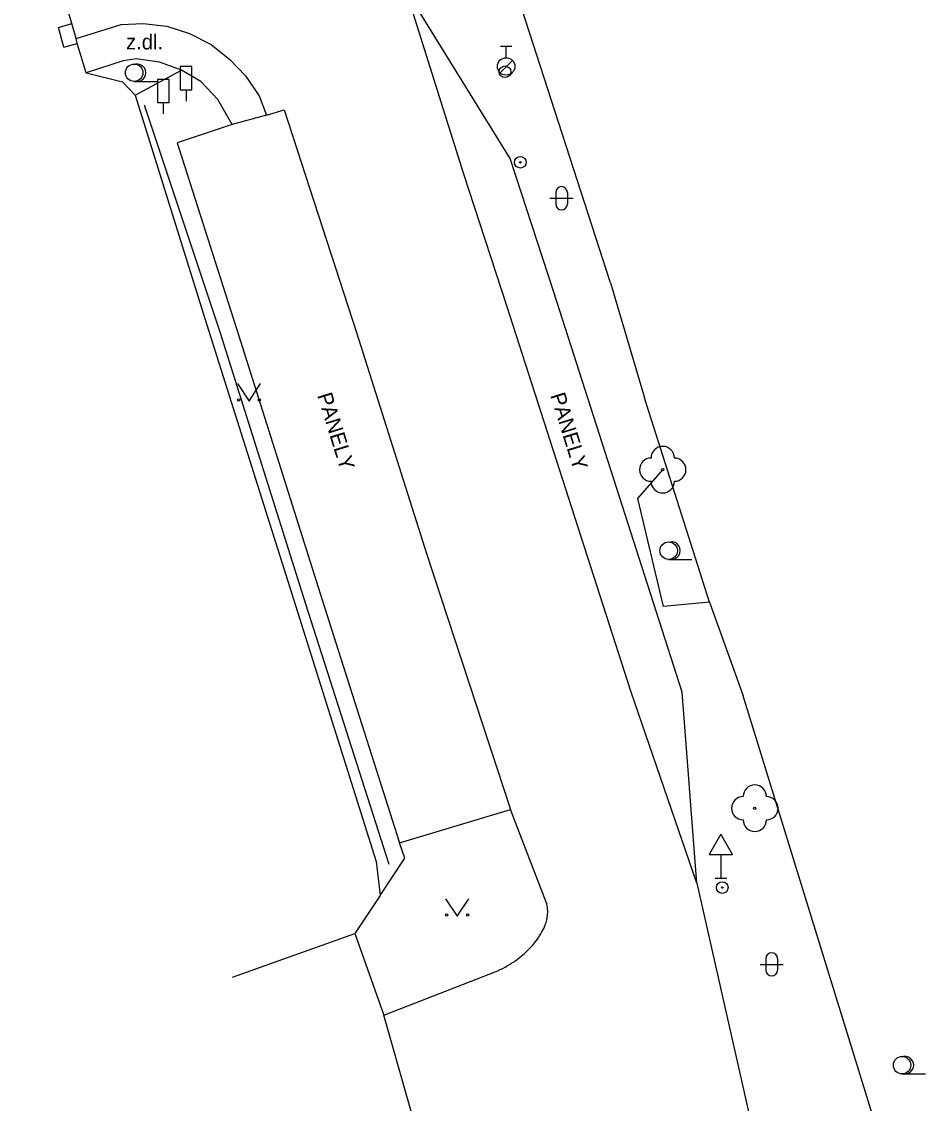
# Model space of a CAD drawing. Extents: x -539244 to -537359, y -1183785 to -1181851.
# Drawn here: x -538156.84 to -538117.99, y -1182044.68 to -1181998.19 of the extents above; entities that cross this region are included whole.
import ezdxf

# ---------------------------------------------------------------- set-up
doc = ezdxf.new("R2010")
doc.units = 0
for name, color, linetype in [('Vrstva 10', 7, 'Continuous'), ('Vrstva 11', 7, 'Continuous'), ('Vrstva 21', 7, 'Continuous'), ('Vrstva 22', 7, 'Continuous'), ('Vrstva 25', 7, 'Continuous'), ('Vrstva 28', 7, 'Continuous'), ('Vrstva 34', 7, 'Continuous'), ('Vrstva 36', 7, 'Continuous'), ('Vrstva 38', 7, 'Continuous'), ('Vrstva 40', 7, 'Continuous'), ('Vrstva 7', 7, 'Continuous'), ('Vrstva 8', 7, 'Continuous')]:
    doc.layers.add(name, color=color, linetype=linetype)

msp = doc.modelspace()

# ---------------------------------------------------------------- linework, layer by layer
at = {"layer": 'Vrstva 10'}
for points in [[(-538137.83, -1182004.75), (-538140.32, -1181996.81)], [(-538154.5, -1181998.92), (-538152.56, -1181998.32), (-538151.62, -1181998.27), (-538150.6, -1181998.39), (-538149.62, -1181998.71), (-538148.69, -1181999.17), (-538147.89, -1181999.82), (-538147.22, -1182000.53), (-538146.63, -1182001.38), (-538146.31, -1182002.21)], [(-538146.31, -1182002.21), (-538145.55, -1182001.99)], [(-538145.55, -1182001.99), (-538142.44, -1182011.55)], [(-538135.98, -1182010.41), (-538137.83, -1182004.75)], [(-538130.64, -1182027.01), (-538135.98, -1182010.41)], [(-538142.44, -1182011.55), (-538139.42, -1182021.1)], [(-538139.42, -1182021.1), (-538135.83, -1182032.05)], [(-538127.81, -1182035.22), (-538130.64, -1182027.01)], [(-538134.29, -1182036.03), (-538135.83, -1182032.05)], [(-538127.81, -1182035.22), (-538125.4, -1182045.87), (-538124.045, -1182050.07), (-538122.69, -1182054.27)], [(-538141.27, -1182040.89), (-538138.875, -1182039.96), (-538136.48, -1182039.03), (-538136.371, -1182038.985), (-538136.264, -1182038.937), (-538136.16, -1182038.886), (-538136.059, -1182038.832), (-538135.961, -1182038.776), (-538135.866, -1182038.719), (-538135.774, -1182038.66), (-538135.686, -1182038.601), (-538135.601, -1182038.541), (-538135.52, -1182038.481), (-538135.442, -1182038.42), (-538135.367, -1182038.36), (-538135.226, -1182038.239), (-538135.099, -1182038.12), (-538134.985, -1182038.004), (-538134.882, -1182037.893), (-538134.791, -1182037.785), (-538134.71, -1182037.682), (-538134.639, -1182037.584), (-538134.576, -1182037.491), (-538134.521, -1182037.402), (-538134.473, -1182037.319), (-538134.432, -1182037.239), (-538134.396, -1182037.165), (-538134.365, -1182037.094), (-538134.338, -1182037.028), (-538134.316, -1182036.965), (-538134.297, -1182036.907), (-538134.267, -1182036.797), (-538134.247, -1182036.7), (-538134.234, -1182036.615), (-538134.227, -1182036.542), (-538134.224, -1182036.477), (-538134.224, -1182036.42), (-538134.229, -1182036.322), (-538134.238, -1182036.248), (-538134.247, -1182036.193), (-538134.266, -1182036.111), (-538134.29, -1182036.03)]]:
    msp.add_lwpolyline(points, dxfattribs=at)
at = {"layer": 'Vrstva 11'}
msp.add_line((-538146.31, -1182002.21), (-538147.79, -1182002.62), dxfattribs=at)
for points in [[(-538135.84, -1182004.08), (-538140.32, -1181996.81)], [(-538149.96, -1182000.28), (-538150.92, -1181999.93), (-538151.91, -1181999.8), (-538152.47, -1181999.88), (-538154.06, -1182000.4)], [(-538147.79, -1182002.62), (-538148.41, -1182001.54), (-538149.13, -1182000.77), (-538149.96, -1182000.28)], [(-538147.79, -1182002.62), (-538150.15, -1182003.41)], [(-538150.15, -1182003.41), (-538147.52, -1182011.65)], [(-538133.96, -1182009.82), (-538135.84, -1182004.08)], [(-538128.44, -1182027.01), (-538133.96, -1182009.82)], [(-538147.52, -1182011.65), (-538143.83, -1182023.31)], [(-538143.83, -1182023.31), (-538140.59, -1182033.48)], [(-538127.81, -1182035.22), (-538128.44, -1182027.01)], [(-538140.59, -1182033.48), (-538135.83, -1182032.05)]]:
    msp.add_lwpolyline(points, dxfattribs=at)
at = {"layer": 'Vrstva 21'}
msp.add_line((-538151.96, -1182001.35), (-538149.96, -1182000.28), dxfattribs=at)
msp.add_lwpolyline([(-538127.27, -1182023.15), (-538129.25, -1182023.33), (-538130.35, -1182018.69), (-538129.28, -1182017.45)], dxfattribs=at)
at = {"layer": 'Vrstva 22'}
for centre in [(-538129.28, -1182017.45), (-538125.32, -1182032)]:
    msp.add_circle(centre, 0.05, dxfattribs=at)
for centre, start, end in [((-538129.28, -1182016.95), 0, 180), ((-538129.78, -1182017.45), 90, 270), ((-538128.78, -1182017.45), 270, 90), ((-538129.28, -1182017.95), 180, 0), ((-538125.32, -1182031.5), 0, 180), ((-538125.82, -1182032), 90, 270), ((-538124.82, -1182032), 270, 90), ((-538125.32, -1182032.5), 180, 0)]:
    msp.add_arc(centre, 0.5, start, end, dxfattribs=at)
at = {"layer": 'Vrstva 25'}
for centre, radius in [((-538135.4, -1182004.24), 0.25), ((-538135.4, -1182004.24), 0.0303), ((-538126.72, -1182035.41), 0.25), ((-538126.72, -1182035.41), 0.0303)]:
    msp.add_circle(centre, radius, dxfattribs=at)
at = {"layer": 'Vrstva 28'}
for p, q in [((-538136.26, -1181999.245), (-538135.76, -1181999.245)), ((-538136.01, -1181999.745), (-538136.01, -1181999.245)), ((-538136.268, -1182000.392), (-538135.738, -1181999.862))]:
    msp.add_line(p, q, dxfattribs=at)
for centre, radius in [((-538136.01, -1182000.12), 0.375), ((-538136.06, -1182000.35), 0.25)]:
    msp.add_circle(centre, radius, dxfattribs=at)
at = {"layer": 'Vrstva 34'}
for p, q in [((-538126.78, -1182033.984), (-538126.78, -1182035)), ((-538127.03, -1182035), (-538126.53, -1182035))]:
    msp.add_line(p, q, dxfattribs=at)
msp.add_lwpolyline([(-538127.28, -1182033.984), (-538126.28, -1182033.984), (-538126.78, -1182033.116)], close=True, dxfattribs=at)
at = {"layer": 'Vrstva 36'}
for p, q in [((-538152.002, -1182000.766), (-538151.002, -1182000.766)), ((-538134.129, -1182005.786), (-538133.129, -1182005.786)), ((-538133.88, -1182005.535), (-538133.88, -1182006.036)), ((-538133.379, -1182005.535), (-538133.379, -1182006.036)), ((-538129.025, -1182021.304), (-538128.025, -1182021.304)), ((-538124.847, -1182038.459), (-538124.847, -1182038.96)), ((-538124.346, -1182038.459), (-538124.346, -1182038.96)), ((-538125.096, -1182038.71), (-538124.096, -1182038.71)), ((-538118.988, -1182043.418), (-538117.988, -1182043.418))]:
    msp.add_line(p, q, dxfattribs=at)
for points in [[(-538147.565, -1182013.75), (-538147.065, -1182014.5), (-538146.565, -1182013.75)], [(-538138.619, -1182035.894), (-538138.119, -1182036.644), (-538137.619, -1182035.894)]]:
    msp.add_lwpolyline(points, dxfattribs=at)
for centre, radius in [((-538152.002, -1182000.391), 0.375), ((-538147.515, -1182014.45), 0.05), ((-538146.616, -1182014.45), 0.05), ((-538129.025, -1182020.929), 0.375), ((-538138.569, -1182036.594), 0.05), ((-538137.67, -1182036.594), 0.05), ((-538118.988, -1182043.043), 0.375)]:
    msp.add_circle(centre, radius, dxfattribs=at)
for centre, radius, start, end in [((-538151.877, -1182000.391), 0.375, 260.4059, 99.5941), ((-538133.629, -1182005.536), 0.25, 0, 180), ((-538133.629, -1182006.036), 0.25, 180, 0), ((-538128.9, -1182020.929), 0.375, 260.4059, 99.5941), ((-538124.596, -1182038.46), 0.25, 0, 180), ((-538124.596, -1182038.96), 0.25, 180, 0), ((-538118.863, -1182043.043), 0.375, 260.4059, 99.5941)]:
    msp.add_arc(centre, radius, start, end, dxfattribs=at)
at = {"layer": 'Vrstva 38'}
for p, q in [((-538149.77, -1182001.126), (-538149.77, -1182001.61)), ((-538150.75, -1182001.676), (-538150.75, -1182002.16))]:
    msp.add_line(p, q, dxfattribs=at)
for points in [[(-538150.019, -1182001.126), (-538149.521, -1182001.126), (-538149.521, -1182000.125), (-538150.019, -1182000.125)], [(-538150.999, -1182001.676), (-538150.501, -1182001.676), (-538150.501, -1182000.675), (-538150.999, -1182000.675)]]:
    msp.add_lwpolyline(points, close=True, dxfattribs=at)
at = {"layer": 'Vrstva 7'}
for p, q in [((-538131.53, -1182009.42), (-538140.59, -1181981.38)), ((-538155.256, -1181998.447), (-538154.68, -1181998.28)), ((-538155.026, -1181999.297), (-538155.256, -1181998.447)), ((-538155.026, -1181999.297), (-538154.45, -1181999.13)), ((-538127.27, -1182023.15), (-538130.06, -1182014.36)), ((-538119.8, -1182046.68), (-538125.82, -1182027.17)), ((-538147.773, -1182039.254), (-538142.51, -1182037.39))]:
    msp.add_line(p, q, dxfattribs=at)
for points in [[(-538154.5, -1181998.92), (-538154.68, -1181998.28)], [(-538154.45, -1181999.13), (-538154.5, -1181998.92)], [(-538154.06, -1182000.4), (-538152.5, -1182000.78), (-538151.96, -1182001.35)], [(-538151.96, -1182001.35), (-538148.96, -1182010.95)], [(-538151.57, -1182001.77), (-538148.32, -1182011.52)], [(-538148.96, -1182010.95), (-538145.31, -1182022.52)], [(-538148.32, -1182011.52), (-538144.63, -1182023.21)], [(-538145.31, -1182022.52), (-538141.6, -1182034.29)], [(-538144.63, -1182023.21), (-538141.06, -1182034.41)], [(-538141.42, -1182035.75), (-538140.36, -1182034.15), (-538140.59, -1182033.48)], [(-538141.6, -1182034.29), (-538141.42, -1182035.75)], [(-538141.42, -1182035.75), (-538142.51, -1182037.39), (-538141.27, -1182040.89)]]:
    msp.add_lwpolyline(points, dxfattribs=at)
at = {"layer": 'Vrstva 8'}
for p, q in [((-538154.68, -1181998.28), (-538156.84, -1181990.84)), ((-538154.06, -1182000.4), (-538154.45, -1181999.13)), ((-538131.53, -1182009.42), (-538130.06, -1182014.36)), ((-538127.27, -1182023.15), (-538125.82, -1182027.17)), ((-538139.54, -1182046.95), (-538141.27, -1182040.89))]:
    msp.add_line(p, q, dxfattribs=at)

# ---------------------------------------------------------------- texts
at = {"layer": 'Vrstva 40'}
msp.add_text('z.dl.', height=0.65, dxfattribs=at).set_placement((-538152.352, -1181999.389))
for p in [(-538144.141, -1182014.253), (-538134.121, -1182014.253)]:
    msp.add_text('PANELY', height=0.65, rotation=287.3042, dxfattribs=at).set_placement(p)

doc.saveas('drawing.dxf')
